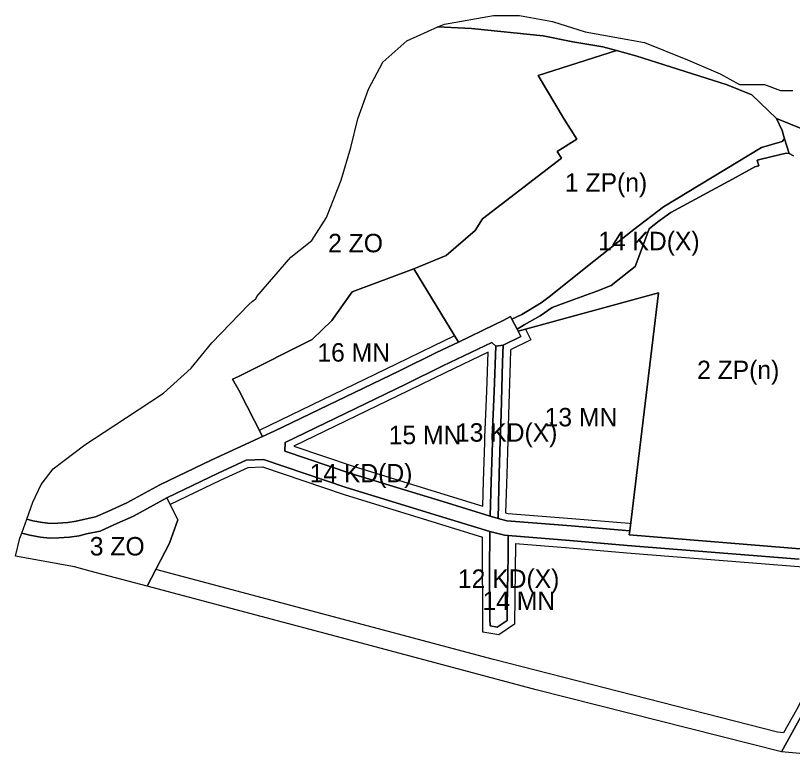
# Model space of a CAD drawing. Extents: x 7424258 to 7426021, y 5551671 to 5553193.
# Drawn here: x 7424258.3 to 7424679.4, y 5551747.9 to 5552149.7 of the extents above; entities that cross this region are included whole.
import ezdxf

# ---------------------------------------------------------------- set-up
doc = ezdxf.new("R2010")
doc.units = 0
for name, color, linetype in [('linie_rozgraniczajace', 7, 'Continuous'), ('linie_zabudowy_nieprzekraczalne', 7, 'Continuous'), ('oznaczenia_przeznaczen', 7, 'Continuous')]:
    doc.layers.add(name, color=color, linetype=linetype)

msp = doc.modelspace()

# ---------------------------------------------------------------- linework, layer by layer
at = {"layer": 'linie_rozgraniczajace'}
for points in [[(7424487.25, 5552143.48), (7424490.76, 5552145.07), (7424517.45, 5552149.68), (7424531.46, 5552149.64), (7424549.35, 5552146.45), (7424567.14, 5552140.87), (7424599.18, 5552135.12), (7424622.53, 5552125.65), (7424640.17, 5552118.07), (7424650.8, 5552112.27), (7424664.3, 5552112.25), (7424673, 5552109), (7424679.62, 5552109.03)], [(7424685.96, 5552087.72), (7424670.82, 5552093.85), (7424657.38, 5552106.68), (7424644.13, 5552112.02), (7424594.51, 5552127.79), (7424584.02, 5552130.67), (7424576.57, 5552132.72), (7424560.46, 5552135.49), (7424544.34, 5552138.63), (7424505.41, 5552142.6), (7424487.25, 5552143.48)], [(7424680.06, 5552073.64), (7424677.62, 5552074.88), (7424675.16, 5552082.9), (7424673.8, 5552087.33), (7424670.82, 5552093.85), (7424685.96, 5552087.72)], [(7424687.92, 5551860.23), (7424590.95, 5551868.06), (7424591.22, 5551870.31), (7424606.9, 5551999.34), (7424530.71, 5551978.58), (7424530.16, 5551979.66), (7424534.06, 5551981.95), (7424542.65, 5551986.91), (7424549.24, 5551991.29), (7424561.53, 5551995.83), (7424573.39, 5552000.22), (7424581.2, 5552003.27), (7424591.66, 5552011.57), (7424594.13, 5552013.54), (7424595.02, 5552015.9), (7424601.76, 5552033.97), (7424606.44, 5552037.78), (7424613.5, 5552042.84), (7424648.86, 5552061.99), (7424659.13, 5552067.61), (7424661.18, 5552068.18), (7424660.29, 5552071.34), (7424668.39, 5552073.22), (7424675.98, 5552074.99), (7424677.62, 5552074.88), (7424680.06, 5552073.64)], [(7424683.16, 5551854.93), (7424589.9, 5551862.39), (7424558.82, 5551864.96), (7424525.39, 5551867.71), (7424523.37, 5551867.87), (7424515.48, 5551869.84), (7424487.55, 5551878.49), (7424437.6, 5551893.83), (7424392.66, 5551909.04), (7424383.39, 5551908.55), (7424368.04, 5551901.48), (7424340.29, 5551888.21), (7424322.19, 5551878.29), (7424311.56, 5551873.45), (7424304.16, 5551870.17), (7424296.84, 5551868.61), (7424292.7, 5551867.65), (7424287.53, 5551866.87), (7424281.71, 5551866.4), (7424276.94, 5551866.29), (7424271.79, 5551866.9), (7424266.06, 5551867.87), (7424261.66, 5551868.98), (7424264.39, 5551876.55), (7424267.71, 5551875.71), (7424272.93, 5551874.83), (7424277.32, 5551874.29), (7424281.29, 5551874.39), (7424286.61, 5551874.82), (7424291.2, 5551875.52), (7424295.1, 5551876.42), (7424301.68, 5551877.81), (7424308.28, 5551880.74), (7424318.6, 5551885.44), (7424336.44, 5551895.22), (7424364.65, 5551908.72), (7424392.09, 5551921.37), (7424398.49, 5551924.26), (7424466.34, 5551957.04), (7424486.44, 5551966.89), (7424498.42, 5551972.64), (7424517.78, 5551981.94), (7424522.91, 5551984.46), (7424526.64, 5551986.4), (7424527.39, 5551984.97), (7424530.16, 5551979.66), (7424530.71, 5551978.58), (7424532.24, 5551975.65), (7424522.61, 5551970.89), (7424518.56, 5551970.46), (7424516.42, 5551972.4), (7424489.94, 5551959.69), (7424469.84, 5551949.85), (7424404.43, 5551918.24), (7424404.33, 5551913.53), (7424440.05, 5551901.44), (7424489.9, 5551886.13), (7424515.54, 5551878.18), (7424519.84, 5551877.03), (7424524.69, 5551875.78), (7424559.48, 5551872.93), (7424591.22, 5551870.31), (7424590.95, 5551868.06), (7424687.92, 5551860.23)], [(7424685.08, 5551771.37), (7424673.44, 5551750.52), (7424540.43, 5551784.11), (7424435.05, 5551812.2), (7424391.52, 5551823.8), (7424329.67, 5551840.29), (7424341.76, 5551863.58), (7424346.29, 5551876.24), (7424340.29, 5551888.21), (7424368.04, 5551901.48), (7424383.39, 5551908.55), (7424392.66, 5551909.04), (7424437.6, 5551893.83), (7424487.55, 5551878.49), (7424515.48, 5551869.84), (7424515.29, 5551848.46), (7424515.4, 5551822.31), (7424515.5, 5551818.73), (7424519.4, 5551818.06), (7424524.72, 5551821.72), (7424524.84, 5551830.11), (7424525.17, 5551846.82), (7424525.28, 5551857.21), (7424525.39, 5551867.71), (7424558.82, 5551864.96), (7424589.9, 5551862.39), (7424683.16, 5551854.93)], [(7424701.33, 5551747.93), (7424673.44, 5551750.52), (7424685.08, 5551771.37)]]:
    msp.add_lwpolyline(points, dxfattribs=at)
for points in [[(7424264.39, 5551876.55), (7424267.75, 5551885.84), (7424272.19, 5551895.33), (7424278.65, 5551903.92), (7424295.81, 5551916.92), (7424311.65, 5551927.22), (7424338.43, 5551944.9), (7424353.45, 5551958.43), (7424364.72, 5551972.25), (7424384.74, 5551992.99), (7424386.59, 5551994.57), (7424388.46, 5551996.13), (7424389.17, 5551997.4), (7424398.33, 5552008), (7424407.48, 5552018.6), (7424418.99, 5552027.7), (7424426.84, 5552040.15), (7424434.82, 5552060.38), (7424440.11, 5552078.14), (7424443.85, 5552093.75), (7424449.66, 5552109.7), (7424457.35, 5552124.46), (7424470.4, 5552135.88), (7424487.25, 5552143.48), (7424505.41, 5552142.6), (7424544.34, 5552138.63), (7424560.46, 5552135.49), (7424576.57, 5552132.72), (7424584.02, 5552130.67), (7424541.51, 5552117.09), (7424555.74, 5552093.44), (7424562.54, 5552082.64), (7424551.95, 5552075.98), (7424554.23, 5552072.4), (7424511.46, 5552039.36), (7424507.43, 5552033.1), (7424491.67, 5552019.55), (7424474.21, 5552012.3), (7424440.72, 5551999.8), (7424429.74, 5551984.39), (7424419.16, 5551974.1), (7424379.19, 5551954), (7424375.98, 5551952.53), (7424379.37, 5551946.49), (7424392.09, 5551921.37), (7424364.65, 5551908.72), (7424336.44, 5551895.22), (7424318.6, 5551885.44), (7424308.28, 5551880.74), (7424301.68, 5551877.81), (7424295.1, 5551876.42), (7424291.2, 5551875.52), (7424286.61, 5551874.82), (7424281.29, 5551874.39), (7424277.32, 5551874.29), (7424272.93, 5551874.83), (7424267.71, 5551875.71)], [(7424474.21, 5552012.3), (7424491.67, 5552019.55), (7424507.43, 5552033.1), (7424511.46, 5552039.36), (7424554.23, 5552072.4), (7424551.95, 5552075.98), (7424562.54, 5552082.64), (7424555.74, 5552093.44), (7424541.51, 5552117.09), (7424584.02, 5552130.67), (7424594.51, 5552127.79), (7424644.13, 5552112.02), (7424657.38, 5552106.68), (7424670.82, 5552093.85), (7424673.8, 5552087.33), (7424675.16, 5552082.9), (7424673.88, 5552081.31), (7424662.64, 5552078.17), (7424609.58, 5552045.97), (7424593.38, 5552033.61), (7424571.78, 5552016.41), (7424547.64, 5551997.15), (7424543.17, 5551993.95), (7424532.77, 5551987.58), (7424527.39, 5551984.97), (7424526.64, 5551986.4), (7424522.91, 5551984.46), (7424517.78, 5551981.94), (7424498.42, 5551972.64)], [(7424527.39, 5551984.97), (7424532.77, 5551987.58), (7424543.17, 5551993.95), (7424547.64, 5551997.15), (7424571.78, 5552016.41), (7424593.38, 5552033.61), (7424609.58, 5552045.97), (7424662.64, 5552078.17), (7424673.88, 5552081.31), (7424675.16, 5552082.9), (7424677.62, 5552074.88), (7424675.98, 5552074.99), (7424668.39, 5552073.22), (7424660.29, 5552071.34), (7424661.18, 5552068.18), (7424659.13, 5552067.61), (7424648.86, 5552061.99), (7424613.5, 5552042.84), (7424606.44, 5552037.78), (7424601.76, 5552033.97), (7424595.02, 5552015.9), (7424594.13, 5552013.54), (7424591.66, 5552011.57), (7424581.2, 5552003.27), (7424573.39, 5552000.22), (7424561.53, 5551995.83), (7424549.24, 5551991.29), (7424542.65, 5551986.91), (7424534.06, 5551981.95), (7424530.16, 5551979.66)], [(7424392.09, 5551921.37), (7424379.37, 5551946.49), (7424375.98, 5551952.53), (7424379.19, 5551954), (7424419.16, 5551974.1), (7424429.74, 5551984.39), (7424440.72, 5551999.8), (7424474.21, 5552012.3), (7424498.42, 5551972.64), (7424486.44, 5551966.89), (7424466.34, 5551957.04), (7424398.49, 5551924.26)], [(7424519.84, 5551877.03), (7424520.53, 5551901.13), (7424521.07, 5551919.12), (7424521.5, 5551933.45), (7424522.34, 5551961.68), (7424522.61, 5551970.89), (7424532.24, 5551975.65), (7424530.71, 5551978.58), (7424606.9, 5551999.34), (7424591.22, 5551870.31), (7424559.48, 5551872.93), (7424524.69, 5551875.78)], [(7424515.54, 5551878.18), (7424489.9, 5551886.13), (7424440.05, 5551901.44), (7424404.33, 5551913.53), (7424404.43, 5551918.24), (7424469.84, 5551949.85), (7424489.94, 5551959.69), (7424516.42, 5551972.4), (7424518.56, 5551970.46), (7424517.71, 5551945.85), (7424516.63, 5551921.09), (7424516.75, 5551918.1), (7424516.03, 5551897.06)], [(7424515.54, 5551878.18), (7424516.03, 5551897.06), (7424516.75, 5551918.1), (7424516.63, 5551921.09), (7424517.71, 5551945.85), (7424518.56, 5551970.46), (7424522.61, 5551970.89), (7424522.34, 5551961.68), (7424521.5, 5551933.45), (7424521.07, 5551919.12), (7424520.53, 5551901.13), (7424519.84, 5551877.03)], [(7424261.66, 5551868.98), (7424266.06, 5551867.87), (7424271.79, 5551866.9), (7424276.94, 5551866.29), (7424281.71, 5551866.4), (7424287.53, 5551866.87), (7424292.7, 5551867.65), (7424296.84, 5551868.61), (7424304.16, 5551870.17), (7424311.56, 5551873.45), (7424322.19, 5551878.29), (7424340.29, 5551888.21), (7424346.29, 5551876.24), (7424341.76, 5551863.58), (7424329.67, 5551840.29), (7424298.8, 5551848.4), (7424290.18, 5551850.67), (7424258.29, 5551856.52), (7424260.67, 5551866.23)], [(7424515.48, 5551869.84), (7424523.37, 5551867.87), (7424525.39, 5551867.71), (7424525.28, 5551857.21), (7424525.17, 5551846.82), (7424524.84, 5551830.11), (7424524.72, 5551821.72), (7424519.4, 5551818.06), (7424515.5, 5551818.73), (7424515.4, 5551822.31), (7424515.29, 5551848.46)]]:
    msp.add_lwpolyline(points, close=True, dxfattribs=at)
at = {"layer": 'linie_zabudowy_nieprzekraczalne'}
for points in [[(7424534.54, 5551979.9), (7424537.68, 5551973.87), (7424526.54, 5551968.37)], [(7424495.96, 5551975.9), (7424484.7, 5551970.49), (7424464.59, 5551960.64), (7424390.29, 5551924.76)], [(7424514.44, 5551967.11), (7424491.21, 5551955.95), (7424471.12, 5551946.12), (7424409.09, 5551916.14)], [(7424511.68, 5551883.57), (7424512.03, 5551897.18), (7424512.75, 5551918.09), (7424512.63, 5551921.1), (7424513.71, 5551946.01), (7424514.44, 5551967.11)], [(7424526.54, 5551968.37), (7424526.34, 5551961.57), (7424525.5, 5551933.33), (7424525.07, 5551919), (7424524.53, 5551901.02), (7424523.93, 5551880.11)], [(7424409.09, 5551916.14), (7424441.28, 5551905.25), (7424491.08, 5551889.96), (7424511.68, 5551883.57)], [(7424342.01, 5551884.59), (7424369.74, 5551897.86), (7424384.36, 5551904.6), (7424392.1, 5551905), (7424436.37, 5551890.02), (7424486.37, 5551874.67), (7424511.47, 5551866.89)], [(7424523.93, 5551880.11), (7424525.36, 5551879.75), (7424559.8, 5551876.91), (7424590.87, 5551874.34), (7424591.7, 5551874.28)], [(7424529.36, 5551863.37), (7424528.69, 5551819.6), (7424520.33, 5551813.84), (7424511.6, 5551815.34), (7424511.47, 5551866.89)], [(7424529.36, 5551863.37), (7424558.49, 5551860.97), (7424589.57, 5551858.4), (7424682.82, 5551850.95), (7424698.68, 5551849.5), (7424701.82, 5551845.97), (7424695.79, 5551820.11), (7424694.21, 5551814.42), (7424683.94, 5551777.76), (7424681.57, 5551773.27), (7424674.58, 5551760.77)], [(7424671.37, 5551761.19), (7424585.07, 5551783.11), (7424517.45, 5551800.42), (7424334.39, 5551849.38)], [(7424674.58, 5551760.77), (7424671.37, 5551761.19)]]:
    msp.add_lwpolyline(points, dxfattribs=at)

# ---------------------------------------------------------------- texts
at = {"layer": 'oznaczenia_przeznaczen'}
for s, p in [('1 ZP(n)', (7424556.11, 5552054.18)), ('14 KD(X)', (7424574.12, 5552022.41)), ('2 ZO', (7424427.74, 5552021.31)), ('16 MN', (7424421.91, 5551962.02)), ('2 ZP(n)', (7424627.73, 5551952.52)), ('13 MN', (7424545.1, 5551926.92)), ('15 MN', (7424460.58, 5551917.26)), ('13 KD(X)', (7424497.03, 5551918.62)), ('14 KD(D)', (7424417.71, 5551896.54)), ('3 ZO', (7424298.54, 5551856.92)), ('12 KD(X)', (7424498.09, 5551839.35)), ('14 MN', (7424511.41, 5551827.34))]:
    msp.add_text(s, height=10, dxfattribs=at).set_placement(p)

doc.saveas('drawing.dxf')
